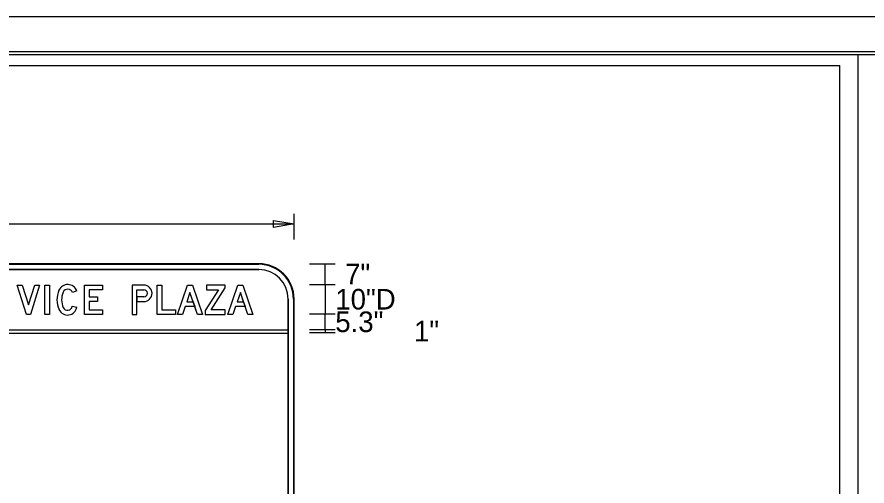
# Model space of a CAD drawing. Extents: x 17890484 to 17890754, y 17897495 to 17897992.
# Drawn here: x 17890540.84 to 17890564.9, y 17897585.59 to 17897598.87 of the extents above; entities that cross this region are included whole.
import ezdxf

# ---------------------------------------------------------------- set-up
doc = ezdxf.new("R2010")
doc.units = 0
for name, color, linetype in [('GSBWFill', 7, 'Continuous'), ('GSColorFill', 7, 'Continuous'), ('GSDims', 7, 'Continuous'), ('GSOutline', 7, 'Continuous'), ('PlotBorder_dp', 7, 'Continuous'), ('SheetBorder_dp', 7, 'Continuous'), ('SheetLinesMisc2_dp', 7, 'Continuous')]:
    doc.layers.add(name, color=color, linetype=linetype)

msp = doc.modelspace()

# ---------------------------------------------------------------- linework, layer by layer
at = {"layer": 'GSBWFill'}
for p, q in [((17890547.683, 17897591.883), (17890529.683, 17897591.883)), ((17890529.683, 17897591.716), (17890547.683, 17897591.716)), ((17890542.536, 17897591.113), (17890542.411, 17897591.067)), ((17890544.23, 17897591.146), (17890544.43, 17897591.146)), ((17890542.404, 17897590.678), (17890542.536, 17897590.658)), ((17890548.517, 17897590.883), (17890548.517, 17897578.883)), ((17890548.683, 17897578.883), (17890548.683, 17897590.883)), ((17890548.517, 17897590.001), (17890528.85, 17897590.001)), ((17890548.517, 17897589.917), (17890548.517, 17897590.001)), ((17890528.85, 17897589.917), (17890548.517, 17897589.917))]:
    msp.add_line(p, q, dxfattribs=at)
for points in [[(17890540.988, 17897591.279), (17890541.165, 17897590.718), (17890541.342, 17897591.279), (17890541.482, 17897591.279), (17890541.219, 17897590.446), (17890541.111, 17897590.446), (17890540.848, 17897591.279)], [(17890541.625, 17897591.279), (17890541.759, 17897591.279), (17890541.759, 17897590.446), (17890541.625, 17897590.446)], [(17890543.264, 17897591.146), (17890542.88, 17897591.146), (17890542.88, 17897590.946), (17890543.123, 17897590.946), (17890543.123, 17897590.812), (17890542.88, 17897590.812), (17890542.88, 17897590.579), (17890543.264, 17897590.579), (17890543.264, 17897590.446), (17890542.747, 17897590.446), (17890542.747, 17897591.279), (17890543.264, 17897591.279)], [(17890544.941, 17897590.579), (17890545.324, 17897590.579), (17890545.324, 17897590.446), (17890544.807, 17897590.446), (17890544.807, 17897591.279), (17890544.941, 17897591.279)], [(17890545.382, 17897590.446), (17890545.665, 17897591.279), (17890545.807, 17897591.279), (17890546.09, 17897590.446), (17890545.949, 17897590.446), (17890545.736, 17897591.073), (17890545.646, 17897590.808), (17890545.826, 17897590.808), (17890545.871, 17897590.675), (17890545.6, 17897590.675), (17890545.522, 17897590.446)], [(17890546.541, 17897591.146), (17890546.167, 17897590.558), (17890546.167, 17897590.446), (17890546.733, 17897590.446), (17890546.733, 17897590.579), (17890546.338, 17897590.579), (17890546.733, 17897591.2), (17890546.733, 17897591.279), (17890546.2, 17897591.279), (17890546.2, 17897591.146)], [(17890546.81, 17897590.446), (17890547.093, 17897591.279), (17890547.235, 17897591.279), (17890547.518, 17897590.446), (17890547.377, 17897590.446), (17890547.164, 17897591.073), (17890547.074, 17897590.808), (17890547.254, 17897590.808), (17890547.3, 17897590.675), (17890547.029, 17897590.675), (17890546.951, 17897590.446)]]:
    msp.add_lwpolyline(points, close=True, dxfattribs=at)
for points in [[(17890544.43, 17897591.279), (17890544.097, 17897591.279), (17890544.097, 17897590.446), (17890544.23, 17897590.446), (17890544.23, 17897591.146)], [(17890544.43, 17897590.946), (17890544.23, 17897590.946), (17890544.23, 17897590.812), (17890544.43, 17897590.812)]]:
    msp.add_lwpolyline(points, dxfattribs=at)
for radius in [1, 0.833]:
    msp.add_arc((17890547.683, 17897590.883), radius, 0, 90, dxfattribs=at)
for centre, major_axis, start_param, end_param in [((17890542.278, 17897591.019), (0, 0.275), 5.061866, 7.434148), ((17890542.278, 17897591.019), (0, 0.142), 5.061866, 7.434148), ((17890544.43, 17897591.046), (0, 0.233), 3.141593, 6.283185), ((17890542.628, 17897590.862), (0, 0.658), 1.150963, 2.004476), ((17890542.628, 17897590.862), (0, 0.525), 1.150963, 2.004476), ((17890544.43, 17897591.046), (0, 0.1), 3.141593, 6.283185), ((17890542.272, 17897590.698), (0, 0.133), 2.004476, 4.564141), ((17890542.272, 17897590.698), (0, 0.267), 2.004476, 4.564141)]:
    msp.add_ellipse(centre, major_axis=major_axis, ratio=0.999994, start_param=start_param, end_param=end_param, dxfattribs=at)
at = {"layer": 'GSColorFill'}
for p, q in [((17890547.683, 17897591.883), (17890529.683, 17897591.883)), ((17890547.683, 17897591.883), (17890529.683, 17897591.883)), ((17890547.683, 17897591.883), (17890529.683, 17897591.883)), ((17890529.683, 17897591.866), (17890547.683, 17897591.866)), ((17890529.683, 17897591.716), (17890547.683, 17897591.716)), ((17890542.536, 17897591.113), (17890542.411, 17897591.067)), ((17890544.23, 17897591.146), (17890544.43, 17897591.146)), ((17890542.404, 17897590.678), (17890542.536, 17897590.658)), ((17890548.517, 17897590.883), (17890548.517, 17897578.883)), ((17890548.667, 17897590.883), (17890548.667, 17897578.883)), ((17890548.683, 17897578.883), (17890548.683, 17897590.883)), ((17890548.683, 17897578.883), (17890548.683, 17897590.883)), ((17890548.683, 17897578.883), (17890548.683, 17897590.883)), ((17890548.517, 17897590.001), (17890528.85, 17897590.001)), ((17890548.517, 17897589.917), (17890548.517, 17897590.001)), ((17890528.85, 17897589.917), (17890548.517, 17897589.917))]:
    msp.add_line(p, q, dxfattribs=at)
for points in [[(17890540.988, 17897591.279), (17890541.165, 17897590.718), (17890541.342, 17897591.279), (17890541.482, 17897591.279), (17890541.219, 17897590.446), (17890541.111, 17897590.446), (17890540.848, 17897591.279)], [(17890541.625, 17897591.279), (17890541.759, 17897591.279), (17890541.759, 17897590.446), (17890541.625, 17897590.446)], [(17890543.264, 17897591.146), (17890542.88, 17897591.146), (17890542.88, 17897590.946), (17890543.123, 17897590.946), (17890543.123, 17897590.812), (17890542.88, 17897590.812), (17890542.88, 17897590.579), (17890543.264, 17897590.579), (17890543.264, 17897590.446), (17890542.747, 17897590.446), (17890542.747, 17897591.279), (17890543.264, 17897591.279)], [(17890544.941, 17897590.579), (17890545.324, 17897590.579), (17890545.324, 17897590.446), (17890544.807, 17897590.446), (17890544.807, 17897591.279), (17890544.941, 17897591.279)], [(17890545.382, 17897590.446), (17890545.665, 17897591.279), (17890545.807, 17897591.279), (17890546.09, 17897590.446), (17890545.949, 17897590.446), (17890545.736, 17897591.073), (17890545.646, 17897590.808), (17890545.826, 17897590.808), (17890545.871, 17897590.675), (17890545.6, 17897590.675), (17890545.522, 17897590.446)], [(17890546.541, 17897591.146), (17890546.167, 17897590.558), (17890546.167, 17897590.446), (17890546.733, 17897590.446), (17890546.733, 17897590.579), (17890546.338, 17897590.579), (17890546.733, 17897591.2), (17890546.733, 17897591.279), (17890546.2, 17897591.279), (17890546.2, 17897591.146)], [(17890546.81, 17897590.446), (17890547.093, 17897591.279), (17890547.235, 17897591.279), (17890547.518, 17897590.446), (17890547.377, 17897590.446), (17890547.164, 17897591.073), (17890547.074, 17897590.808), (17890547.254, 17897590.808), (17890547.3, 17897590.675), (17890547.029, 17897590.675), (17890546.951, 17897590.446)]]:
    msp.add_lwpolyline(points, close=True, dxfattribs=at)
for points in [[(17890544.43, 17897591.279), (17890544.097, 17897591.279), (17890544.097, 17897590.446), (17890544.23, 17897590.446), (17890544.23, 17897591.146)], [(17890544.43, 17897590.946), (17890544.23, 17897590.946), (17890544.23, 17897590.812), (17890544.43, 17897590.812)]]:
    msp.add_lwpolyline(points, dxfattribs=at)
for radius in [1, 1, 1, 0.983, 0.833]:
    msp.add_arc((17890547.683, 17897590.883), radius, 0, 90, dxfattribs=at)
for centre, major_axis, start_param, end_param in [((17890542.278, 17897591.019), (0, 0.275), 5.061866, 7.434148), ((17890542.278, 17897591.019), (0, 0.142), 5.061866, 7.434148), ((17890544.43, 17897591.046), (0, 0.233), 3.141593, 6.283185), ((17890542.628, 17897590.862), (0, 0.658), 1.150963, 2.004476), ((17890542.628, 17897590.862), (0, 0.525), 1.150963, 2.004476), ((17890544.43, 17897591.046), (0, 0.1), 3.141593, 6.283185), ((17890542.272, 17897590.698), (0, 0.133), 2.004476, 4.564141), ((17890542.272, 17897590.698), (0, 0.267), 2.004476, 4.564141)]:
    msp.add_ellipse(centre, major_axis=major_axis, ratio=0.999994, start_param=start_param, end_param=end_param, dxfattribs=at)
at = {"layer": 'GSDims'}
for p, q in [((17890548.683, 17897592.57), (17890548.683, 17897593.299)), ((17890528.683, 17897593.008), (17890548.683, 17897593.008)), ((17890549.121, 17897591.883), (17890549.85, 17897591.883)), ((17890549.558, 17897591.296), (17890549.558, 17897591.883)), ((17890549.121, 17897591.296), (17890549.85, 17897591.296)), ((17890549.121, 17897591.296), (17890549.85, 17897591.296)), ((17890549.558, 17897591.296), (17890549.558, 17897590.462)), ((17890549.121, 17897590.462), (17890549.85, 17897590.462)), ((17890549.121, 17897590.462), (17890549.85, 17897590.462)), ((17890549.558, 17897590.017), (17890549.558, 17897590.462)), ((17890549.121, 17897590.017), (17890549.85, 17897590.017)), ((17890549.121, 17897590.017), (17890549.85, 17897590.017)), ((17890549.558, 17897590.017), (17890549.558, 17897589.934)), ((17890549.121, 17897589.934), (17890549.85, 17897589.934)), ((17890549.121, 17897589.934), (17890549.85, 17897589.934))]:
    msp.add_line(p, q, dxfattribs=at)
msp.add_lwpolyline([(17890548.683, 17897593.008), (17890548.1, 17897592.911), (17890548.1, 17897593.105)], close=True, dxfattribs=at)
at = {"layer": 'GSOutline'}
for p, q in [((17890547.683, 17897591.883), (17890529.683, 17897591.883)), ((17890547.683, 17897591.716), (17890529.683, 17897591.716)), ((17890542.536, 17897591.113), (17890542.411, 17897591.067)), ((17890542.404, 17897590.678), (17890542.536, 17897590.658)), ((17890544.23, 17897590.812), (17890544.43, 17897590.812)), ((17890548.517, 17897578.883), (17890548.517, 17897590.883)), ((17890548.683, 17897578.883), (17890548.683, 17897590.883)), ((17890548.517, 17897590.001), (17890528.85, 17897590.001)), ((17890548.517, 17897589.917), (17890548.517, 17897590.001)), ((17890528.85, 17897589.917), (17890548.517, 17897589.917))]:
    msp.add_line(p, q, dxfattribs=at)
for points in [[(17890540.988, 17897591.279), (17890541.165, 17897590.718), (17890541.342, 17897591.279), (17890541.482, 17897591.279), (17890541.219, 17897590.446), (17890541.111, 17897590.446), (17890540.848, 17897591.279)], [(17890541.625, 17897591.279), (17890541.759, 17897591.279), (17890541.759, 17897590.446), (17890541.625, 17897590.446)], [(17890543.264, 17897591.146), (17890542.88, 17897591.146), (17890542.88, 17897590.946), (17890543.123, 17897590.946), (17890543.123, 17897590.812), (17890542.88, 17897590.812), (17890542.88, 17897590.579), (17890543.264, 17897590.579), (17890543.264, 17897590.446), (17890542.747, 17897590.446), (17890542.747, 17897591.279), (17890543.264, 17897591.279)], [(17890544.941, 17897590.579), (17890545.324, 17897590.579), (17890545.324, 17897590.446), (17890544.807, 17897590.446), (17890544.807, 17897591.279), (17890544.941, 17897591.279)], [(17890545.6, 17897590.675), (17890545.522, 17897590.446), (17890545.382, 17897590.446), (17890545.665, 17897591.279), (17890545.807, 17897591.279), (17890546.09, 17897590.446), (17890545.949, 17897590.446), (17890545.871, 17897590.675)], [(17890546.541, 17897591.146), (17890546.167, 17897590.558), (17890546.167, 17897590.446), (17890546.733, 17897590.446), (17890546.733, 17897590.579), (17890546.338, 17897590.579), (17890546.733, 17897591.2), (17890546.733, 17897591.279), (17890546.2, 17897591.279), (17890546.2, 17897591.146)], [(17890547.029, 17897590.675), (17890546.951, 17897590.446), (17890546.81, 17897590.446), (17890547.093, 17897591.279), (17890547.235, 17897591.279), (17890547.518, 17897590.446), (17890547.377, 17897590.446), (17890547.3, 17897590.675)], [(17890545.646, 17897590.808), (17890545.826, 17897590.808), (17890545.736, 17897591.073)], [(17890547.074, 17897590.808), (17890547.254, 17897590.808), (17890547.164, 17897591.073)]]:
    msp.add_lwpolyline(points, close=True, dxfattribs=at)
for points in [[(17890544.43, 17897591.279), (17890544.097, 17897591.279), (17890544.097, 17897590.446), (17890544.23, 17897590.446), (17890544.23, 17897590.812)], [(17890544.43, 17897590.946), (17890544.23, 17897590.946), (17890544.23, 17897591.146), (17890544.43, 17897591.146)]]:
    msp.add_lwpolyline(points, dxfattribs=at)
for radius in [1, 0.833]:
    msp.add_arc((17890547.683, 17897590.883), radius, 0, 90, dxfattribs=at)
for centre, major_axis, start_param, end_param in [((17890542.278, 17897591.019), (0, 0.275), 5.061866, 7.434148), ((17890542.278, 17897591.019), (0, 0.142), 5.061866, 7.434148), ((17890544.43, 17897591.046), (0, 0.233), 3.141593, 6.283185), ((17890542.628, 17897590.862), (0, 0.658), 1.150963, 2.004476), ((17890542.628, 17897590.862), (0, 0.525), 1.150963, 2.004476), ((17890544.43, 17897591.046), (0, 0.1), 3.141593, 6.283185), ((17890542.272, 17897590.698), (0, 0.133), 2.004476, 4.564141), ((17890542.272, 17897590.698), (0, 0.267), 2.004476, 4.564141)]:
    msp.add_ellipse(centre, major_axis=major_axis, ratio=0.999994, start_param=start_param, end_param=end_param, dxfattribs=at)
at = {"layer": 'PlotBorder_dp'}
msp.add_lwpolyline([(17890483.9, 17897494.956), (17890645.649, 17897494.956), (17890645.649, 17897598.868), (17890483.9, 17897598.868)], close=True, dxfattribs=at)
at = {"layer": 'SheetBorder_dp'}
msp.add_line((17890489.292, 17897597.887), (17890640.258, 17897597.887), dxfattribs=at)
at = {"layer": 'SheetLinesMisc2_dp'}
for p, q in [((17890489.413, 17897597.808), (17890639.869, 17897597.808)), ((17890564.641, 17897597.808), (17890564.641, 17897504.15)), ((17890512.958, 17897597.496), (17890564.13, 17897597.496)), ((17890564.13, 17897572.57), (17890564.13, 17897597.496))]:
    msp.add_line(p, q, dxfattribs=at)

# ---------------------------------------------------------------- texts
at = {"layer": 'GSDims'}
for s, p in [('7"', (17890550.127, 17897591.298)), ('10"D', (17890549.85, 17897590.587)), ('5.3"', (17890549.85, 17897589.948)), ('1"', (17890552.076, 17897589.684))]:
    msp.add_text(s, height=0.5833, dxfattribs=at).set_placement(p)

doc.saveas('drawing.dxf')
